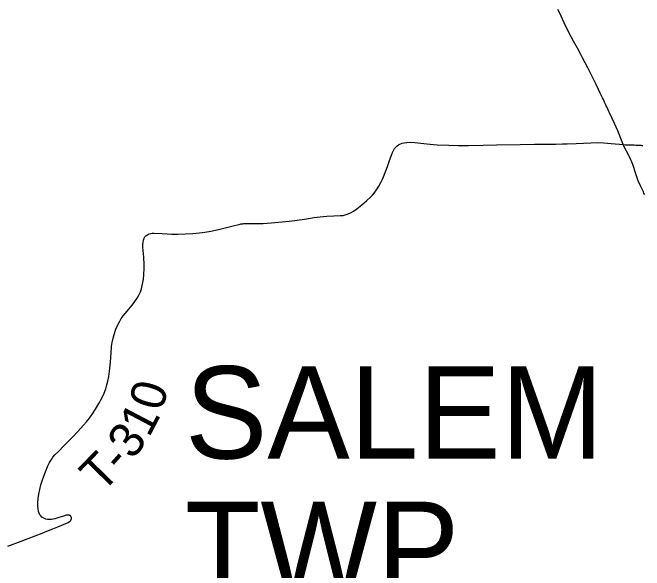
# Model space of a CAD drawing. Extents: x 0 to 34, y 0 to 22.
# Drawn here: x 3.105 to 4.132, y 15.027 to 15.933 of the extents above; entities that cross this region are included whole.
import ezdxf

# ---------------------------------------------------------------- set-up
doc = ezdxf.new("R2010")
doc.units = 0
for name, color, linetype in [('GM_X_Township_Road', 7, 'Continuous'), ('GM_X_Township_Road_Text', 7, 'Continuous'), ('GM_X_Township_Text', 7, 'Continuous')]:
    doc.layers.add(name, color=color, linetype=linetype)

msp = doc.modelspace()

# ---------------------------------------------------------------- linework, layer by layer
at = {"layer": 'GM_X_Township_Road'}
for points in [[(4.0972, 15.7186), (4.0952, 15.723), (4.0882, 15.7409), (4.0831, 15.7529), (4.0794, 15.7608), (4.0749, 15.7703), (4.0739, 15.7726), (4.0704, 15.7798), (4.0696, 15.7815), (4.0683, 15.7843), (4.0668, 15.7877), (4.066, 15.7894), (4.0649, 15.7916), (4.0636, 15.7943), (4.0598, 15.8021), (4.0569, 15.8082), (4.0531, 15.816), (4.0397, 15.8433), (4.031, 15.8597), (4.0281, 15.8652), (4.0264, 15.8685), (4.0249, 15.8712), (4.0208, 15.8788), (4.0165, 15.8864), (4.0096, 15.8996), (4.0015, 15.9163), (3.9966, 15.927), (3.9943, 15.932), (3.9911, 15.9381)], [(3.0974, 15.0666), (3.1149, 15.073), (3.1306, 15.0789), (3.1532, 15.0876), (3.1607, 15.0906), (3.1705, 15.0945), (3.1785, 15.0976), (3.192, 15.1032), (3.1953, 15.1047), (3.1979, 15.1064), (3.1988, 15.1072), (3.1996, 15.1081), (3.2001, 15.1089), (3.2005, 15.1095), (3.201, 15.1112), (3.2009, 15.1125), (3.2008, 15.1132), (3.2006, 15.1137), (3.2001, 15.1146), (3.1997, 15.1152), (3.1988, 15.116), (3.1977, 15.1165), (3.1969, 15.1168), (3.1959, 15.1169), (3.195, 15.117), (3.1941, 15.1169), (3.1923, 15.1166), (3.1881, 15.1153), (3.1805, 15.1128), (3.174, 15.111), (3.1685, 15.11), (3.1648, 15.1097), (3.1617, 15.1098), (3.1593, 15.1102), (3.157, 15.1111), (3.1548, 15.1122), (3.1528, 15.1137), (3.1511, 15.1155), (3.1497, 15.1175), (3.1486, 15.1198), (3.1476, 15.1227), (3.1467, 15.127), (3.1463, 15.1319), (3.1462, 15.1369), (3.1468, 15.1437), (3.1478, 15.1511), (3.1493, 15.1584), (3.1513, 15.1661), (3.1543, 15.1756), (3.1586, 15.1872), (3.1627, 15.197), (3.1654, 15.2025), (3.1682, 15.2073), (3.1708, 15.2109), (3.1741, 15.2146), (3.1803, 15.2208), (3.188, 15.2287), (3.1955, 15.2363), (3.2032, 15.2442), (3.2111, 15.2529), (3.2204, 15.2628), (3.2254, 15.2683), (3.23, 15.2741), (3.2351, 15.2812), (3.2401, 15.289), (3.2455, 15.2981), (3.2501, 15.3069), (3.2538, 15.3148), (3.2565, 15.3217), (3.2586, 15.3282), (3.2601, 15.3342), (3.2617, 15.342), (3.2629, 15.3506), (3.2643, 15.3654), (3.2652, 15.3803), (3.2661, 15.3907), (3.2671, 15.3974), (3.2684, 15.4041), (3.2701, 15.41), (3.2731, 15.4187), (3.2757, 15.4249), (3.2787, 15.4309), (3.2819, 15.4361), (3.2851, 15.4406), (3.2914, 15.4482), (3.2993, 15.4578), (3.3037, 15.4637), (3.3075, 15.4694), (3.3108, 15.4753), (3.3129, 15.4797), (3.3146, 15.4843), (3.316, 15.4896), (3.317, 15.4944), (3.3179, 15.4999), (3.3187, 15.5079), (3.3192, 15.5172), (3.3191, 15.5234), (3.3183, 15.5358), (3.3168, 15.5519), (3.3167, 15.5539), (3.3168, 15.5563), (3.3172, 15.56), (3.318, 15.5636), (3.3191, 15.5665), (3.3203, 15.5687), (3.3219, 15.5706), (3.3233, 15.5717), (3.3249, 15.5727), (3.3272, 15.5737), (3.3298, 15.5743), (3.3321, 15.5745), (3.3346, 15.5746), (3.3482, 15.5743), (3.3562, 15.5739), (3.3642, 15.5734), (3.3736, 15.5732), (3.3854, 15.5735), (3.3978, 15.5742), (3.4089, 15.5751), (3.4175, 15.5762), (3.4273, 15.578), (3.44, 15.5809), (3.4551, 15.5847), (3.4659, 15.5873), (3.4708, 15.5884), (3.4749, 15.5894), (3.4762, 15.5897), (3.478, 15.59), (3.4793, 15.5901), (3.4807, 15.5902), (3.4821, 15.5902), (3.4906, 15.5902), (3.5005, 15.5902), (3.5123, 15.5906), (3.5253, 15.5915), (3.537, 15.5925), (3.5544, 15.5941), (3.5673, 15.5957), (3.5796, 15.5976), (3.5949, 15.6001), (3.6048, 15.6013), (3.6159, 15.6023), (3.6271, 15.603), (3.6376, 15.6033), (3.642, 15.6037), (3.6456, 15.6045), (3.6503, 15.606), (3.6543, 15.6078), (3.6592, 15.6105), (3.6643, 15.6141), (3.6725, 15.6206), (3.6804, 15.6275), (3.6871, 15.634), (3.6897, 15.6367), (3.6925, 15.64), (3.6963, 15.6449), (3.7004, 15.6511), (3.7037, 15.6571), (3.7068, 15.6638), (3.7117, 15.6758), (3.7145, 15.6833), (3.7172, 15.6909), (3.7208, 15.7015), (3.7224, 15.7056), (3.7238, 15.709), (3.7258, 15.7122), (3.7278, 15.7146), (3.7295, 15.7163), (3.732, 15.7182), (3.7353, 15.7199), (3.7382, 15.721), (3.7412, 15.7217), (3.7455, 15.7222), (3.7511, 15.7223), (3.7586, 15.7219), (3.7784, 15.7198), (3.7951, 15.7185), (3.8137, 15.7175), (3.8292, 15.717), (3.846, 15.717), (3.8696, 15.7175), (3.8913, 15.718), (3.9297, 15.7187), (3.9533, 15.7191), (3.9676, 15.7192), (3.9875, 15.7194), (3.9987, 15.7197), (4.0061, 15.7199), (4.021, 15.7206), (4.0445, 15.7217), (4.0556, 15.7218), (4.0656, 15.7214), (4.0777, 15.7204), (4.0839, 15.7199), (4.0909, 15.7192), (4.0972, 15.7186)], [(4.0972, 15.7186), (4.1009, 15.7185), (4.1046, 15.7184), (4.1087, 15.7183), (4.1122, 15.7182), (4.1152, 15.7181), (4.1176, 15.7179), (4.1197, 15.7178), (4.1213, 15.7177), (4.1235, 15.7176), (4.1256, 15.7175), (4.1275, 15.7173), (4.1292, 15.7173)], [(4.1321, 15.6375), (4.1309, 15.6396), (4.13, 15.6419), (4.1272, 15.6474), (4.1253, 15.6519), (4.1217, 15.6598), (4.12, 15.6644), (4.1173, 15.6727), (4.1134, 15.6844), (4.111, 15.6908), (4.1105, 15.6919), (4.1098, 15.6936), (4.1075, 15.6987), (4.1065, 15.701), (4.0983, 15.7163), (4.0972, 15.7186)]]:
    msp.add_lwpolyline(points, dxfattribs=at)

# ---------------------------------------------------------------- texts
at = {"layer": 'GM_X_Township_Road_Text'}
for s, rotation, p in [('0', 73.9283, (3.3477, 15.2842)), ('1', 62.2811, (3.3267, 15.2415)), ('3', 53.3153, (3.3006, 15.2053)), ('T', 45.7152, (3.2501, 15.1512)), ('-', 48.3401, (3.2817, 15.1837))]:
    msp.add_text(s, height=0.0568, rotation=rotation, dxfattribs=at).set_placement(p)
at = {"layer": 'GM_X_Township_Text'}
for s, p in [('SALEM', (3.3853, 15.2087)), ('TWP', (3.3853, 14.9887))]:
    msp.add_text(s, height=0.15, rotation=0, dxfattribs=at).set_placement(p)

doc.saveas('drawing.dxf')
